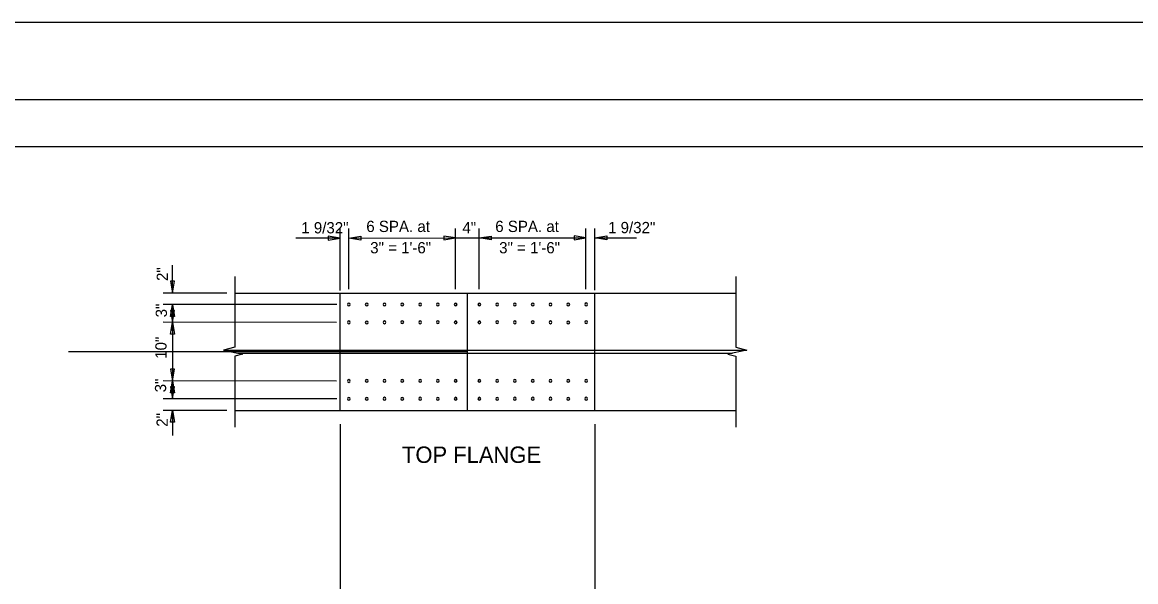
# Model space of a CAD drawing. Extents: x 4944 to 17449, y 3824 to 49087.
# Drawn here: x 13033 to 14172, y 40650 to 41222 of the extents above; entities that cross this region are included whole.
import ezdxf

# ---------------------------------------------------------------- set-up
doc = ezdxf.new("R2010")
doc.units = 0
for name, color, linetype in [('1', 7, 'Continuous'), ('2', 7, 'Continuous'), ('36_S_LINES', 7, 'Continuous'), ('37_S_TXT', 7, 'Continuous'), ('3A', 7, 'Continuous'), ('7', 7, 'Continuous'), ('BEAM', 7, 'Continuous'), ('DIM', 7, 'Continuous'), ('Level 14', 7, 'Continuous'), ('Level 25', 7, 'Continuous')]:
    doc.layers.add(name, color=color, linetype=linetype)

msp = doc.modelspace()

# ---------------------------------------------------------------- linework, layer by layer
at = {"layer": '1'}
for centre, start, end in [((13367.6, 40933.2), 0, 180), ((13367.6, 40933.2), 180, 0), ((13385.8, 40933.2), 0, 180), ((13385.8, 40933.2), 180, 0), ((13404, 40933.2), 0, 180), ((13404, 40933.2), 180, 0), ((13422.2, 40933.3), 0, 180), ((13422.2, 40933.3), 180, 0), ((13440.4, 40933.2), 0, 180), ((13440.4, 40933.2), 180, 0), ((13458.6, 40933.3), 0, 180), ((13458.6, 40933.3), 180, 0), ((13476.8, 40933.2), 0, 180), ((13476.8, 40933.2), 180, 0), ((13501, 40933.2), 0, 180), ((13501, 40933.2), 180, 0), ((13519.2, 40933.3), 0, 180), ((13519.2, 40933.3), 180, 0), ((13537.4, 40933.2), 0, 180), ((13537.4, 40933.2), 180, 0), ((13555.6, 40933.3), 0, 180), ((13555.6, 40933.3), 180, 0), ((13573.8, 40933.2), 0, 180), ((13573.8, 40933.2), 180, 0), ((13592, 40933.2), 0, 180), ((13592, 40933.2), 180, 0), ((13610.2, 40933.4), 0, 180), ((13610.2, 40933.4), 180, 0), ((13367.6, 40915), 0, 180), ((13367.6, 40915), 180, 0), ((13385.8, 40914.9), 0, 180), ((13385.8, 40914.9), 180, 0), ((13404, 40915), 0, 180), ((13404, 40915), 180, 0), ((13422.2, 40915.1), 0, 180), ((13422.2, 40915.1), 180, 0), ((13440.4, 40915), 0, 180), ((13440.4, 40915), 180, 0), ((13458.6, 40915.1), 0, 180), ((13458.6, 40915.1), 180, 0), ((13476.8, 40915), 0, 180), ((13476.8, 40915), 180, 0), ((13501, 40915), 0, 180), ((13501, 40915), 180, 0), ((13519.2, 40915.1), 0, 180), ((13519.2, 40915.1), 180, 0), ((13537.4, 40915), 0, 180), ((13537.4, 40915), 180, 0), ((13555.6, 40915.1), 0, 180), ((13555.6, 40915.1), 180, 0), ((13573.8, 40915), 0, 180), ((13573.8, 40915), 180, 0), ((13592, 40914.9), 0, 180), ((13592, 40914.9), 180, 0), ((13610.2, 40915.1), 0, 180), ((13610.2, 40915.1), 180, 0), ((13367.6, 40855), 0, 180), ((13367.6, 40855), 180, 0), ((13385.8, 40855.1), 0, 180), ((13385.8, 40855.1), 180, 0), ((13404, 40855.1), 0, 180), ((13404, 40855.1), 180, 0), ((13422.2, 40855.1), 0, 180), ((13422.2, 40855.1), 180, 0), ((13440.4, 40855.1), 0, 180), ((13440.4, 40855.1), 180, 0), ((13458.6, 40855.1), 0, 180), ((13458.6, 40855.1), 180, 0), ((13476.8, 40855.1), 0, 180), ((13476.8, 40855.1), 180, 0), ((13501, 40855.1), 0, 180), ((13501, 40855.1), 180, 0), ((13519.2, 40855.1), 0, 180), ((13519.2, 40855.1), 180, 0), ((13537.4, 40855.1), 0, 180), ((13537.4, 40855.1), 180, 0), ((13555.6, 40855.2), 0, 180), ((13555.6, 40855.2), 180, 0), ((13573.8, 40855.1), 0, 180), ((13573.8, 40855.1), 180, 0), ((13592, 40855.1), 0, 180), ((13592, 40855.1), 180, 0), ((13610.2, 40855.1), 0, 180), ((13610.2, 40855.1), 180, 0), ((13367.6, 40836.7), 0, 180), ((13367.6, 40836.7), 180, 0), ((13385.8, 40836.8), 0, 180), ((13385.8, 40836.8), 180, 0), ((13404, 40836.9), 0, 180), ((13404, 40836.9), 180, 0), ((13422.2, 40836.8), 0, 180), ((13422.2, 40836.8), 180, 0), ((13440.4, 40836.9), 0, 180), ((13440.4, 40836.9), 180, 0), ((13458.6, 40836.8), 0, 180), ((13458.6, 40836.8), 180, 0), ((13476.8, 40836.9), 0, 180), ((13476.8, 40836.9), 180, 0), ((13501, 40836.9), 0, 180), ((13501, 40836.9), 180, 0), ((13519.2, 40836.8), 0, 180), ((13519.2, 40836.8), 180, 0), ((13537.4, 40836.9), 0, 180), ((13537.4, 40836.9), 180, 0), ((13555.6, 40836.9), 0, 180), ((13555.6, 40836.9), 180, 0), ((13573.8, 40836.9), 0, 180), ((13573.8, 40836.9), 180, 0), ((13592, 40836.8), 0, 180), ((13592, 40836.8), 180, 0), ((13610.2, 40836.9), 0, 180), ((13610.2, 40836.9), 180, 0)]:
    msp.add_arc(centre, 1.42, start, end, dxfattribs=at)
at = {"layer": '2'}
msp.add_line((13488.9, 40825), (13488.9, 40945), dxfattribs=at)
at = {"layer": '36_S_LINES'}
for p, q in [((13358.6, 40947.7), (13358.6, 41010.9)), ((13619.2, 40947.8), (13619.2, 41011)), ((13358.6, 41001.2), (13313.4, 41001.2)), ((13367.7, 41001.2), (13476.8, 41001.3)), ((13476.8, 41001.3), (13501.2, 41001.3)), ((13501.2, 41001.3), (13610.1, 41001.3)), ((13619.2, 41001.3), (13661.9, 41001.3)), ((13187.3, 40945), (13187.3, 40973.4)), ((13250.8, 40962), (13250.8, 40889.6)), ((13763.4, 40962), (13763.4, 40889.6)), ((13242.6, 40945), (13177.6, 40945)), ((13187.3, 40933.2), (13187.3, 40915.1)), ((13187.3, 40933.2), (13187.3, 40915.1)), ((13187.3, 40921.1), (13187.3, 40849)), ((13187.3, 40921.1), (13187.3, 40842.9)), ((13250.8, 40889.6), (13239.5, 40886.4)), ((13763.4, 40889.6), (13774.7, 40886.4)), ((13239.5, 40886.4), (13258.9, 40882.6)), ((13258.9, 40882.6), (13250.8, 40880.4)), ((13250.8, 40880.4), (13250.8, 40807.7)), ((13774.7, 40886.4), (13755.3, 40882.6)), ((13755.3, 40882.6), (13763.4, 40880.4)), ((13763.4, 40880.4), (13763.4, 40807.7)), ((13187.3, 40836.9), (13187.3, 40855.1)), ((13187.3, 40836.9), (13187.3, 40855.1)), ((13242.6, 40825), (13177.6, 40825)), ((13187.3, 40825), (13187.3, 40799.4))]:
    msp.add_line(p, q, dxfattribs=at)
for points in [[(13346.5, 41003.3), (13346.5, 40999.2), (13358.6, 41001.2)], [(13379.8, 41003.3), (13379.8, 40999.2), (13367.7, 41001.2)], [(13464.6, 41003.3), (13464.6, 40999.3), (13476.8, 41001.3)], [(13513.2, 41003.3), (13513.2, 40999.3), (13501, 41001.3)], [(13598, 41003.4), (13598, 40999.3), (13610.1, 41001.3)], [(13631.4, 41003.4), (13631.4, 40999.3), (13619.2, 41001.3)], [(13189.3, 40957.2), (13185.2, 40957.2), (13187.3, 40945)], [(13188.3, 40953), (13186.2, 40953), (13187.3, 40945)], [(13188.3, 40953), (13186.2, 40953), (13187.3, 40945)], [(13189.3, 40921.1), (13185.2, 40921.1), (13187.3, 40933.2)], [(13188.3, 40925.3), (13186.2, 40925.3), (13187.3, 40933.2)], [(13188.3, 40925.3), (13186.2, 40925.3), (13187.3, 40933.2)], [(13189.3, 40927.2), (13185.2, 40927.2), (13187.3, 40915.1)], [(13188.3, 40923.1), (13186.2, 40923.1), (13187.3, 40915.1)], [(13188.3, 40923.1), (13186.2, 40923.1), (13187.3, 40915.1)], [(13189.3, 40902.9), (13185.2, 40902.9), (13187.3, 40915.1)], [(13188.3, 40907.1), (13186.2, 40907.1), (13187.3, 40915.1)], [(13188.3, 40907.1), (13186.2, 40907.1), (13187.3, 40915.1)], [(13189.3, 40867.2), (13185.2, 40867.2), (13187.3, 40855.1)], [(13189.3, 40842.9), (13185.2, 40842.9), (13187.3, 40855.1)], [(13188.3, 40863.1), (13186.2, 40863.1), (13187.3, 40855.1)], [(13188.3, 40863.1), (13186.2, 40863.1), (13187.3, 40855.1)], [(13188.3, 40847.1), (13186.2, 40847.1), (13187.3, 40855.1)], [(13188.3, 40847.1), (13186.2, 40847.1), (13187.3, 40855.1)], [(13189.3, 40849), (13185.2, 40849), (13187.3, 40836.9)], [(13188.3, 40844.9), (13186.2, 40844.9), (13187.3, 40836.9)], [(13188.3, 40844.9), (13186.2, 40844.9), (13187.3, 40836.9)], [(13189.3, 40812.9), (13185.2, 40812.9), (13187.3, 40825)], [(13188.3, 40817), (13186.2, 40817), (13187.3, 40825)], [(13188.3, 40817), (13186.2, 40817), (13187.3, 40825)]]:
    msp.add_lwpolyline(points, close=True, dxfattribs=at)
at = {"layer": '37_S_TXT'}
msp.add_lwpolyline([(12345.1, 41222), (15801.2, 41222), (15801.2, 38917.9), (12345.1, 38917.9)], close=True, dxfattribs=at)
at = {"layer": '3A'}
for p, q in [((13367.7, 40948.8), (13367.7, 41010.9)), ((13476.8, 40948.8), (13476.8, 41010.9)), ((13501, 40948.8), (13501, 41010.9)), ((13610.1, 40948.9), (13610.1, 41011)), ((13355.3, 40933.2), (13177.6, 40933.2)), ((13355, 40915), (13177.6, 40915.1)), ((13355, 40855), (13177.6, 40855.1)), ((13355.3, 40836.8), (13177.6, 40836.9))]:
    msp.add_line(p, q, dxfattribs=at)
at = {"layer": '7'}
for p, q in [((13240, 40886.5), (13774.2, 40886.5)), ((13254.2, 40883.5), (13760, 40883.5))]:
    msp.add_line(p, q, dxfattribs=at)
at = {"layer": 'DEFPOINTS'}
for p, q in [((13488.9, 40885), (13080.8, 40885)), ((13358.6, 40810.9), (13358.6, 40500.5)), ((13619.2, 40810.9), (13619.2, 40500.5))]:
    msp.add_line(p, q, dxfattribs=at)
at = {"layer": 'DIM'}
msp.add_lwpolyline([(12502.3, 41142.8), (15766.4, 41142.8), (15766.4, 39030.7), (12502.3, 39030.7)], close=True, dxfattribs=at)
at = {"layer": 'Level 14'}
msp.add_lwpolyline([(15713.6, 39078.7), (12689.5, 39078.7), (12689.5, 41094.8), (15713.6, 41094.8)], close=True, dxfattribs=at)
at = {"layer": 'Level 25'}
for p, q in [((13250.8, 40945), (13763.4, 40945)), ((13358.6, 40825), (13358.6, 40945)), ((13619.2, 40825.1), (13619.2, 40945.1)), ((13250.8, 40825), (13763.4, 40825))]:
    msp.add_line(p, q, dxfattribs=at)

# ---------------------------------------------------------------- texts
at = {"layer": '3A'}
for s, p in [('1 9/32"', (13318.9, 41006)), ('6 SPA. at', (13385.4, 41007.4)), ('4"', (13483.7, 41006.1)), ('6 SPA. at', (13517.3, 41007.4)), ('1 9/32"', (13632.7, 41006.2)), ('3" = 1\'-6"', (13389.4, 40985.6)), ('3" = 1\'-6"', (13521.3, 40985.6))]:
    msp.add_text(s, height=11.52, dxfattribs=at).set_placement(p)
for s, p in [('2"', (13182.5, 40957.3)), ('3"', (13181.5, 40920.1)), ('10"', (13181.1, 40877.7)), ('3"', (13180.7, 40843.4)), ('2"', (13182.3, 40808.2))]:
    msp.add_text(s, height=11.52, rotation=90, dxfattribs=at).set_placement(p)
at = {"layer": 'BEAM'}
msp.add_text('TOP FLANGE', height=16.8, dxfattribs=at).set_placement((13421.9, 40771.2))

doc.saveas('drawing.dxf')
